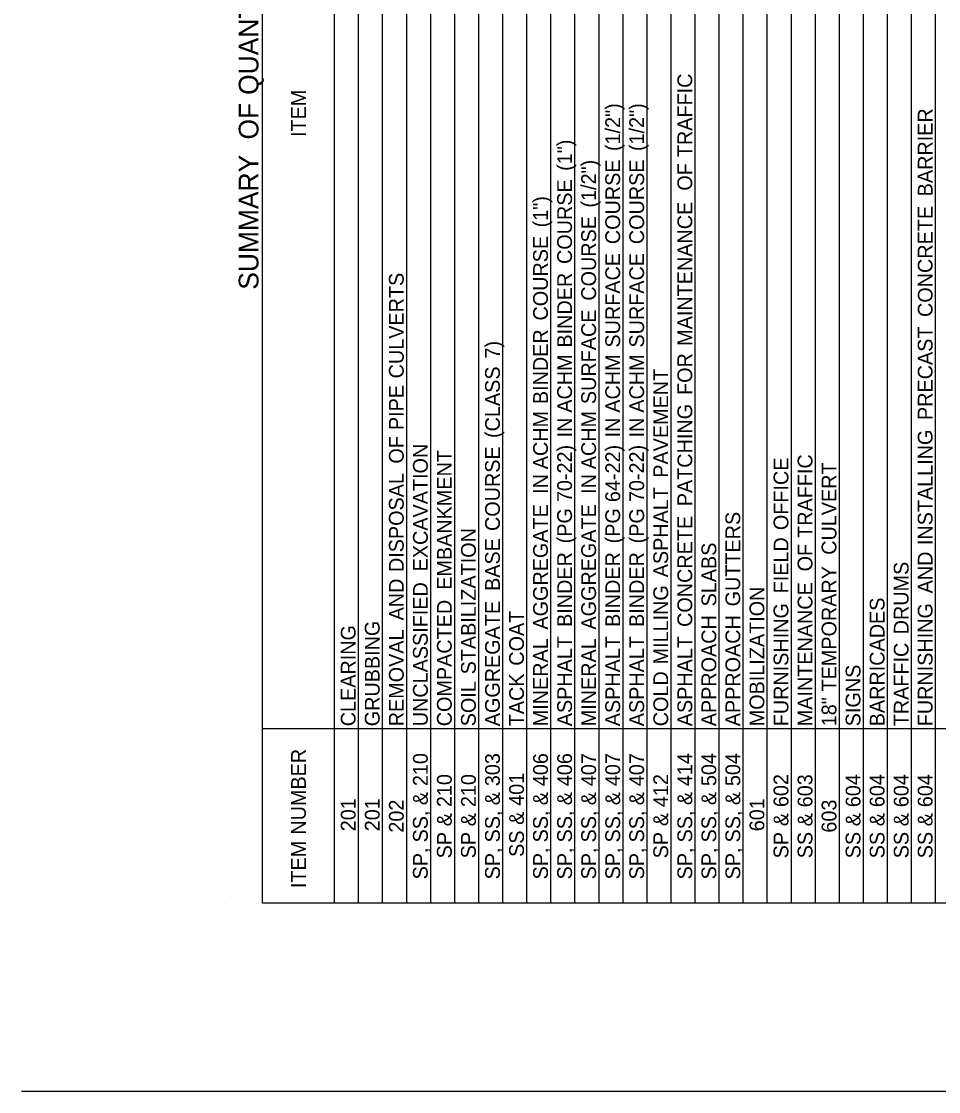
# Model space of a CAD drawing. Extents: x 1334737.6 to 1334769.2, y 402732.2 to 402752.
# Drawn here: x 1334737.56 to 1334746.86, y 402732.19 to 402743.03 of the extents above; entities that cross this region are included whole.
import ezdxf

# ---------------------------------------------------------------- set-up
doc = ezdxf.new("R2010")
doc.units = 0
doc.layers.add('Default', color=7, linetype='Continuous')
doc.layers.add('R_No Plot', color=7, linetype='Continuous')

msp = doc.modelspace()

# ---------------------------------------------------------------- linework, layer by layer
at = {"layer": 'Default'}
for p, q in [((1334740.008, 402734.097), (1334740.008, 402750.83)), ((1334740.74, 402734.097), (1334740.74, 402750.83)), ((1334740.983, 402735.864), (1334740.983, 402750.83)), ((1334741.227, 402734.097), (1334741.227, 402750.83)), ((1334741.471, 402734.097), (1334741.471, 402750.83)), ((1334741.715, 402734.097), (1334741.715, 402750.83)), ((1334741.958, 402734.097), (1334741.958, 402750.83)), ((1334742.202, 402734.097), (1334742.202, 402750.83)), ((1334742.446, 402734.097), (1334742.446, 402750.83)), ((1334742.69, 402734.097), (1334742.69, 402750.83)), ((1334742.933, 402734.097), (1334742.933, 402750.83)), ((1334743.177, 402734.097), (1334743.177, 402750.83)), ((1334743.421, 402734.097), (1334743.421, 402750.83)), ((1334743.665, 402734.097), (1334743.665, 402750.83)), ((1334743.908, 402734.097), (1334743.908, 402750.83)), ((1334744.152, 402734.097), (1334744.152, 402750.83)), ((1334744.396, 402734.097), (1334744.396, 402750.83)), ((1334744.64, 402734.097), (1334744.64, 402750.83)), ((1334744.883, 402734.097), (1334744.883, 402750.83)), ((1334745.127, 402734.097), (1334745.127, 402750.83)), ((1334745.371, 402734.097), (1334745.371, 402750.83)), ((1334745.615, 402734.097), (1334745.615, 402750.83)), ((1334745.858, 402734.097), (1334745.858, 402750.83)), ((1334746.102, 402734.097), (1334746.102, 402750.83)), ((1334746.346, 402734.097), (1334746.346, 402750.83)), ((1334746.59, 402734.097), (1334746.59, 402750.83)), ((1334746.833, 402734.097), (1334746.833, 402750.83)), ((1334740.983, 402734.097), (1334740.983, 402746.15)), ((1334740.008, 402734.097), (1334740.008, 402735.864)), ((1334756.096, 402735.864), (1334740.008, 402735.864)), ((1334740.983, 402735.864), (1334740.74, 402735.864)), ((1334740.983, 402734.097), (1334740.983, 402735.864)), ((1334739.631, 402734.097), (1334739.631, 402734.097)), ((1334761.215, 402734.097), (1334740.008, 402734.097))]:
    msp.add_line(p, q, dxfattribs=at)
at = {"layer": 'R_No Plot'}
msp.add_line((1334769.182, 402732.187), (1334737.564, 402732.187), dxfattribs=at)

# ---------------------------------------------------------------- texts
at = {"layer": 'Default'}
for s, height, p in [(' QUANTITIES', 0.2, (1334739.968, 402742.213)), (' TRAFFIC', 0.15, (1334744.366, 402741.601)), ('ITEM', 0.15, (1334740.449, 402741.861)), (' OF', 0.2, (1334739.968, 402741.761)), (' (1/2")', 0.15, (1334743.635, 402741.663)), (' (1/2")', 0.15, (1334743.878, 402741.663)), (' BARRIER', 0.15, (1334746.803, 402741.204)), (' (1")', 0.15, (1334743.147, 402741.462)), (' SUMMARY', 0.2, (1334739.968, 402740.239)), (' (1/2")', 0.15, (1334743.391, 402741.09)), (' COURSE', 0.15, (1334743.635, 402740.719)), (' COURSE', 0.15, (1334743.878, 402740.719)), (' OF', 0.15, (1334744.366, 402741.261)), (' COURSE', 0.15, (1334743.147, 402740.518)), (' (1")', 0.15, (1334742.903, 402740.889)), (' MAINTENANCE', 0.15, (1334744.366, 402739.689)), (' CONCRETE', 0.15, (1334746.803, 402739.981)), (' COURSE', 0.15, (1334743.391, 402740.146)), (' COURSE', 0.15, (1334742.903, 402739.945)), (' SURFACE', 0.15, (1334743.635, 402739.671)), (' SURFACE', 0.15, (1334743.878, 402739.671)), (' CULVERTS', 0.15, (1334741.441, 402739.359)), (' BINDER', 0.15, (1334743.147, 402739.671)), (' SURFACE', 0.15, (1334743.391, 402739.098)), (' BINDER', 0.15, (1334742.903, 402739.098)), (' PRECAST', 0.15, (1334746.803, 402738.937)), (' 7)', 0.15, (1334742.416, 402739.56)), (' FOR', 0.15, (1334744.366, 402739.191)), (' ACHM', 0.15, (1334743.147, 402739.011)), (' ACHM', 0.15, (1334743.635, 402739.011)), (' ACHM', 0.15, (1334743.878, 402739.011)), (' (CLASS', 0.15, (1334742.416, 402738.755)), (' PAVEMENT', 0.15, (1334744.122, 402738.352)), (' PIPE', 0.15, (1334741.441, 402738.835)), (' PATCHING', 0.15, (1334744.366, 402738.063)), (' ACHM', 0.15, (1334742.903, 402738.438)), (' ACHM', 0.15, (1334743.391, 402738.438)), (' IN', 0.15, (1334743.147, 402738.761)), (' IN', 0.15, (1334743.635, 402738.761)), (' IN', 0.15, (1334743.878, 402738.761)), (' OF', 0.15, (1334741.441, 402738.495)), (' INSTALLING', 0.15, (1334746.803, 402737.669)), (' EXCAVATION', 0.15, (1334741.685, 402737.403)), (' EMBANKMENT', 0.15, (1334741.928, 402737.217)), (' COURSE', 0.15, (1334742.416, 402737.812)), (' 70-22)', 0.15, (1334743.147, 402738.105)), (' 64-22)', 0.15, (1334743.635, 402738.105)), (' 70-22)', 0.15, (1334743.878, 402738.105)), (' OFFICE', 0.15, (1334745.341, 402737.821)), (' TRAFFIC', 0.15, (1334745.585, 402737.743)), (' CULVERT', 0.15, (1334745.828, 402737.571)), (' DISPOSAL', 0.15, (1334741.441, 402737.396)), (' IN', 0.15, (1334742.903, 402738.188)), (' IN', 0.15, (1334743.391, 402738.188)), (' ASPHALT', 0.15, (1334744.122, 402737.343)), (' AGGREGATE', 0.15, (1334742.903, 402736.813)), (' (PG', 0.15, (1334743.147, 402737.687)), (' AGGREGATE', 0.15, (1334743.391, 402736.813)), (' (PG', 0.15, (1334743.635, 402737.687)), (' (PG', 0.15, (1334743.878, 402737.687)), (' GUTTERS', 0.15, (1334744.853, 402737.048)), (' CONCRETE', 0.15, (1334744.366, 402736.84)), (' STABILIZATION', 0.15, (1334742.172, 402736.359)), (' BASE', 0.15, (1334742.416, 402737.205)), (' SLABS', 0.15, (1334744.61, 402737.048)), (' FIELD', 0.15, (1334745.341, 402737.18)), (' OF', 0.15, (1334745.585, 402737.403)), (' BINDER', 0.15, (1334743.147, 402736.84)), (' BINDER', 0.15, (1334743.635, 402736.84)), (' BINDER', 0.15, (1334743.878, 402736.84)), (' AND', 0.15, (1334746.803, 402737.18)), (' TEMPORARY', 0.15, (1334745.828, 402736.186)), (' DRUMS', 0.15, (1334746.56, 402736.765)), (' AND', 0.15, (1334741.441, 402736.906)), ('UNCLASSIFIED', 0.15, (1334741.685, 402735.889)), (' MILLING', 0.15, (1334744.122, 402736.46)), ('MOBILIZATION', 0.15, (1334745.097, 402735.889)), ('MAINTENANCE', 0.15, (1334745.585, 402735.889)), ('BARRICADES', 0.15, (1334746.316, 402735.889)), ('COMPACTED', 0.15, (1334741.928, 402735.889)), ('AGGREGATE', 0.15, (1334742.416, 402735.889)), (' COAT', 0.15, (1334742.66, 402736.447)), ('FURNISHING', 0.15, (1334745.341, 402735.889)), ('FURNISHING', 0.15, (1334746.803, 402735.889)), ('APPROACH', 0.15, (1334744.61, 402735.889)), ('APPROACH', 0.15, (1334744.853, 402735.889)), ('CLEARING', 0.15, (1334740.953, 402735.889)), ('GRUBBING', 0.15, (1334741.197, 402735.889)), ('REMOVAL', 0.15, (1334741.441, 402735.889)), ('MINERAL', 0.15, (1334742.903, 402735.889)), ('ASPHALT', 0.15, (1334743.147, 402735.889)), ('MINERAL', 0.15, (1334743.391, 402735.889)), ('ASPHALT', 0.15, (1334743.635, 402735.889)), ('ASPHALT', 0.15, (1334743.878, 402735.889)), ('ASPHALT', 0.15, (1334744.366, 402735.889)), ('TRAFFIC', 0.15, (1334746.56, 402735.889)), ('TACK', 0.15, (1334742.66, 402735.889)), ('COLD', 0.15, (1334744.122, 402735.889)), ('SIGNS', 0.15, (1334746.072, 402735.889)), ('SOIL', 0.15, (1334742.172, 402735.889)), ('18"', 0.15, (1334745.828, 402735.889)), (' NUMBER', 0.15, (1334740.449, 402734.735)), (' 210', 0.15, (1334741.685, 402735.227)), (' 303', 0.15, (1334742.416, 402735.226)), (' 406', 0.15, (1334742.903, 402735.226)), (' 406', 0.15, (1334743.147, 402735.226)), (' 407', 0.15, (1334743.391, 402735.226)), (' 407', 0.15, (1334743.635, 402735.226)), (' 407', 0.15, (1334743.878, 402735.226)), (' 414', 0.15, (1334744.366, 402735.227)), (' 504', 0.15, (1334744.61, 402735.227)), (' 504', 0.15, (1334744.853, 402735.227)), (' 210', 0.15, (1334741.928, 402735.014)), (' 210', 0.15, (1334742.172, 402735.014)), (' 401', 0.15, (1334742.66, 402735.027)), (' 412', 0.15, (1334744.122, 402735.014)), (' 602', 0.15, (1334745.341, 402735.014)), (' 603', 0.15, (1334745.585, 402735.012)), (' 604', 0.15, (1334746.072, 402735.013)), (' 604', 0.15, (1334746.316, 402735.013)), (' 604', 0.15, (1334746.56, 402735.013)), (' 604', 0.15, (1334746.803, 402735.013)), (' &', 0.15, (1334741.685, 402735.034)), (' &', 0.15, (1334742.416, 402735.033)), (' &', 0.15, (1334742.903, 402735.033)), (' &', 0.15, (1334743.147, 402735.033)), (' &', 0.15, (1334743.391, 402735.033)), (' &', 0.15, (1334743.635, 402735.033)), (' &', 0.15, (1334743.878, 402735.033)), (' &', 0.15, (1334744.366, 402735.034)), (' &', 0.15, (1334744.61, 402735.034)), (' &', 0.15, (1334744.853, 402735.034)), ('201', 0.15, (1334740.953, 402734.825)), ('201', 0.15, (1334741.197, 402734.825)), ('202', 0.15, (1334741.441, 402734.811)), ('601', 0.15, (1334745.097, 402734.825)), ('603', 0.15, (1334745.828, 402734.811)), (' SS,', 0.15, (1334741.685, 402734.656)), (' &', 0.15, (1334741.928, 402734.82)), (' &', 0.15, (1334742.172, 402734.82)), (' SS,', 0.15, (1334742.416, 402734.656)), (' &', 0.15, (1334742.66, 402734.834)), (' SS,', 0.15, (1334742.903, 402734.656)), (' SS,', 0.15, (1334743.147, 402734.656)), (' SS,', 0.15, (1334743.391, 402734.656)), (' SS,', 0.15, (1334743.635, 402734.656)), (' SS,', 0.15, (1334743.878, 402734.656)), (' &', 0.15, (1334744.122, 402734.821)), (' SS,', 0.15, (1334744.366, 402734.656)), (' SS,', 0.15, (1334744.61, 402734.656)), (' SS,', 0.15, (1334744.853, 402734.656)), (' &', 0.15, (1334745.341, 402734.821)), (' &', 0.15, (1334745.585, 402734.819)), (' &', 0.15, (1334746.072, 402734.82)), (' &', 0.15, (1334746.316, 402734.82)), (' &', 0.15, (1334746.56, 402734.82)), (' &', 0.15, (1334746.803, 402734.82)), ('SP', 0.15, (1334741.928, 402734.55)), ('SP', 0.15, (1334742.172, 402734.55)), ('SS', 0.15, (1334742.66, 402734.565)), ('SP', 0.15, (1334744.122, 402734.55)), ('SP', 0.15, (1334745.341, 402734.55)), ('SS', 0.15, (1334745.585, 402734.551)), ('SS', 0.15, (1334746.072, 402734.551)), ('SS', 0.15, (1334746.316, 402734.551)), ('SS', 0.15, (1334746.56, 402734.551)), ('SS', 0.15, (1334746.803, 402734.551)), ('ITEM', 0.15, (1334740.449, 402734.249)), ('SP,', 0.15, (1334741.685, 402734.337)), ('SP,', 0.15, (1334742.416, 402734.337)), ('SP,', 0.15, (1334742.903, 402734.337)), ('SP,', 0.15, (1334743.147, 402734.337)), ('SP,', 0.15, (1334743.391, 402734.337)), ('SP,', 0.15, (1334743.635, 402734.337)), ('SP,', 0.15, (1334743.878, 402734.337)), ('SP,', 0.15, (1334744.366, 402734.337)), ('SP,', 0.15, (1334744.61, 402734.337)), ('SP,', 0.15, (1334744.853, 402734.337))]:
    msp.add_text(s, height=height, rotation=90, dxfattribs=at).set_placement(p)

doc.saveas('drawing.dxf')
